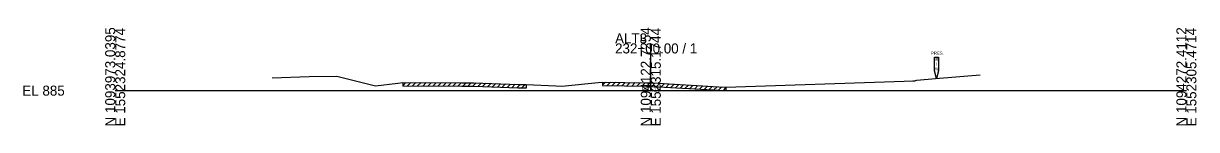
# Model space of a CAD drawing. Extents: x -26 to 1303, y -10 to 19582.
# Drawn here: x -25.7 to 302.8, y 5490.3 to 5517.6 of the extents above; entities that cross this region are included whole.
import ezdxf

# ---------------------------------------------------------------- set-up
doc = ezdxf.new("R2010")
doc.units = 0
for name, color, linetype in [('Default', 7, 'Continuous'), ('RD_GPK_XS_Cell', 7, 'Continuous'), ('RD_XS_ExGround', 7, 'Continuous'), ('RD_XS_ExPaveRet', 7, 'Continuous'), ('RD_XS_ExRW', 7, 'Continuous'), ('RD_XS_TX_Elev_EX', 7, 'Continuous')]:
    doc.layers.add(name, color=color, linetype=linetype)

msp = doc.modelspace()

# ---------------------------------------------------------------- linework, layer by layer
at = {"layer": 'RD_GPK_XS_Cell'}
for p, q in [((150, 5500), (150, 5513.18)), ((0, 5500), (150, 5500)), ((150, 5500), (300, 5500))]:
    msp.add_line(p, q, dxfattribs=at)
at = {"layer": 'RD_XS_ExGround'}
msp.add_lwpolyline([(43.97, 5503.57), (54.34, 5503.9), (62.1, 5504.03), (71.06, 5501.81), (72.92, 5501.34), (79.2, 5502.08), (80.52, 5502.28), (97.09, 5502.16), (100.46, 5502.15), (112.91, 5501.75), (115.06, 5501.69), (123.36, 5501.35), (125.09, 5501.29), (135.23, 5502.24), (136.45, 5502.39), (148.79, 5502.17), (150, 5502.15), (150.45, 5502.14), (169.06, 5501.07), (171.03, 5500.98), (221, 5502.66), (223.36, 5502.75), (223.92, 5502.76), (224.52, 5502.96), (229.74, 5503.34), (242.26, 5504.39)], dxfattribs=at)
at = {"layer": 'RD_XS_ExPaveRet'}
for p, q in [((80.52, 5502.28), (80.52, 5501.28)), ((80.52, 5501.35), (81.44, 5502.27)), ((81.9, 5501.32), (82.84, 5502.26)), ((83.3, 5501.31), (84.24, 5502.25)), ((84.7, 5501.3), (85.65, 5502.24)), ((86.11, 5501.29), (87.05, 5502.23)), ((87.51, 5501.28), (88.46, 5502.22)), ((88.92, 5501.27), (89.86, 5502.21)), ((90.32, 5501.26), (91.27, 5502.2)), ((91.73, 5501.25), (92.67, 5502.19)), ((93.13, 5501.24), (94.07, 5502.18)), ((94.54, 5501.23), (95.48, 5502.17)), ((95.94, 5501.22), (96.88, 5502.17)), ((97.35, 5501.21), (98.29, 5502.16)), ((98.75, 5501.21), (99.7, 5502.15)), ((100.16, 5501.2), (101.09, 5502.13)), ((101.54, 5501.16), (102.46, 5502.08)), ((102.91, 5501.12), (103.83, 5502.04)), ((104.28, 5501.08), (105.2, 5502)), ((105.65, 5501.03), (106.57, 5501.95)), ((107.02, 5500.99), (107.94, 5501.91)), ((108.39, 5500.95), (109.31, 5501.87)), ((109.76, 5500.9), (110.68, 5501.82)), ((111.13, 5500.86), (112.06, 5501.78)), ((112.51, 5500.82), (113.43, 5501.74)), ((113.88, 5500.78), (114.8, 5501.7)), ((115.06, 5501.69), (115.06, 5500.69)), ((136.45, 5502.39), (136.45, 5501.39)), ((136.45, 5501.54), (137.29, 5502.38)), ((137.75, 5501.42), (138.68, 5502.35)), ((139.14, 5501.39), (140.07, 5502.33)), ((140.53, 5501.37), (141.46, 5502.3)), ((141.92, 5501.34), (142.85, 5502.28)), ((143.31, 5501.32), (144.24, 5502.25)), ((144.7, 5501.29), (145.63, 5502.23)), ((146.09, 5501.27), (147.02, 5502.2)), ((147.47, 5501.25), (148.41, 5502.18)), ((148.86, 5501.22), (149.8, 5502.15)), ((150.25, 5501.19), (151.16, 5502.1)), ((151.6, 5501.12), (152.49, 5502.02)), ((152.93, 5501.05), (153.83, 5501.95)), ((154.27, 5500.97), (155.17, 5501.87)), ((155.61, 5500.89), (156.51, 5501.79)), ((156.95, 5500.82), (157.85, 5501.72)), ((158.28, 5500.74), (159.18, 5501.64)), ((159.62, 5500.67), (160.52, 5501.56)), ((160.96, 5500.59), (161.86, 5501.49)), ((162.3, 5500.51), (163.2, 5501.41)), ((163.64, 5500.44), (164.53, 5501.33)), ((164.97, 5500.36), (165.87, 5501.26)), ((166.31, 5500.28), (167.21, 5501.18)), ((167.65, 5500.21), (168.55, 5501.1)), ((168.99, 5500.13), (169.89, 5501.03)), ((170.33, 5500.06), (171.03, 5500.76)), ((171.03, 5500.98), (171.03, 5499.98))]:
    msp.add_line(p, q, dxfattribs=at)
for points in [[(80.52, 5501.33), (97.07, 5501.21), (100.46, 5501.2), (112.89, 5500.8), (115.06, 5500.74)], [(136.45, 5501.44), (148.77, 5501.22), (150, 5501.2), (150.45, 5501.19), (169.04, 5500.13), (171.03, 5500.03)]]:
    msp.add_lwpolyline(points, dxfattribs=at)
at = {"layer": 'RD_XS_ExRW'}
msp.add_lwpolyline([(229.45, 5509.38), (230.55, 5509.38), (230.55, 5505.55), (230, 5503.36), (229.45, 5505.55)], close=True, dxfattribs=at)

# ---------------------------------------------------------------- texts
at = {"layer": 'Default'}
msp.add_text('-', height=0.0001, dxfattribs=at).set_placement((0, 5500))
at = {"layer": 'RD_GPK_XS_Cell'}
for s, p in [('N 1093973.0395', (0, 5490)), ('E 1552324.8774', (2.8, 5490)), ('N 1094122.7254', (150, 5490)), ('E 1552315.1744', (152.8, 5490)), ('N 1094272.4112', (300, 5490)), ('E 1552305.4714', (302.8, 5490))]:
    msp.add_text(s, height=2.8, rotation=90, dxfattribs=at).set_placement(p)
for s, p in [('ALT3', (140, 5513.18)), ('232+00.00 / 1', (140, 5510.38)), ('EL 885', (-26, 5498.6))]:
    msp.add_text(s, height=2.8, dxfattribs=at).set_placement(p)
at = {"layer": 'RD_XS_ExRW'}
for s, p in [('PRES.', (228.45, 5510)), ('W', (229.53, 5505.66)), ('R', (229.71, 5508.28)), ('/', (229.83, 5506.97))]:
    msp.add_text(s, height=0.875, dxfattribs=at).set_placement(p)
at = {"layer": 'RD_XS_TX_Elev_EX'}
msp.add_text('887.15', height=1.25, dxfattribs=at).set_placement((147.44, 5499.72))

doc.saveas('drawing.dxf')
